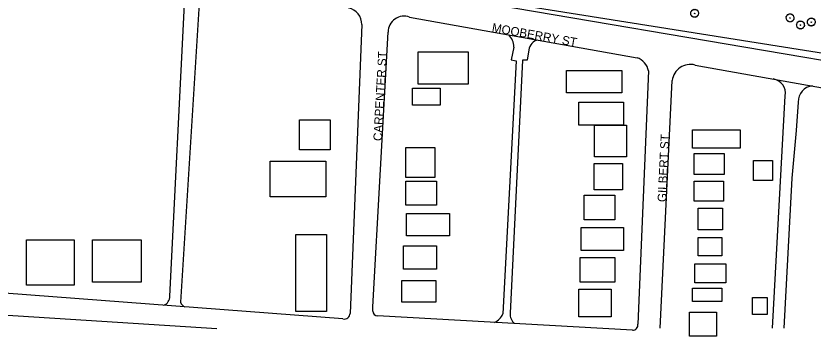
# Model space of a CAD drawing. Extents: x -9648 to 41057, y -12373 to 40276.
# Drawn here: x 11005 to 11921, y -5404 to -5031 of the extents above; entities that cross this region are included whole.
import ezdxf

# ---------------------------------------------------------------- set-up
doc = ezdxf.new("R2010")
doc.units = 0
for name, color, linetype in [('Default', 7, 'Continuous'), ('PM_X_Stop_Line', 7, 'Continuous'), ('SC_Scratch1', 7, 'Continuous'), ('SH_Data', 7, 'Continuous')]:
    doc.layers.add(name, color=color, linetype=linetype)

# ---------------------------------------------------------------- blocks, each defined once
blk = doc.blocks.new('15_PIN')
at = {"layer": 'Default'}
for p, q in [((-2.8, 0), (2.8, 0)), ((0, 2.8), (0, -2.8))]:
    blk.add_line(p, q, dxfattribs=at)
for centre, start, end in [((-25.5, 4.5), 275.99, 64.01), ((-25.9, -1.5), 289.3234, 77.3433), ((-23.8, 10.3), 262.6567, 50.6766), ((-20.8, 15.5), 249.3234, 37.3433), ((-16.7, 19.8), 235.99, 24.01), ((-11.6, 23.2), 222.6567, 10.6766), ((-6, 25.2), 209.3234, 357.3433), ((0, 25.9), 195.99, 344.01), ((6, 25.2), 182.6567, 330.6766), ((11.6, 23.2), 169.3234, 317.3433), ((16.7, 19.8), 155.99, 304.01), ((20.8, 15.5), 142.6567, 290.6766), ((23.8, 10.3), 129.3234, 277.3433), ((25.5, 4.5), 115.99, 264.01), ((25.9, -1.5), 102.6567, 250.6766), ((-24.8, -7.4), 302.6567, 90.6766), ((-22.4, -13), 315.99, 104.01), ((-18.8, -17.8), 329.3234, 117.3433), ((-14.2, -21.6), 342.6567, 130.6766), ((-8.9, -24.3), 355.99, 144.01), ((-3, -25.7), 9.3234, 157.3433), ((3, -25.7), 22.6567, 170.6766), ((8.9, -24.3), 35.99, 184.01), ((14.2, -21.6), 49.3234, 197.3433), ((18.8, -17.8), 62.6567, 210.6767), ((22.4, -13), 75.99, 224.01), ((24.8, -7.4), 89.3234, 237.3433)]:
    blk.add_arc(centre, 3.05, start, end, dxfattribs=at)

msp = doc.modelspace()

# ---------------------------------------------------------------- linework, layer by layer
at = {"layer": 'PM_X_Stop_Line'}
msp.add_arc((9361.23, -8468.95), 3904.03, 82.5, 82.5, dxfattribs=at)
at = {"layer": 'SH_Data'}
for p, q in [((11181.96, -5352.77), (11199.57, -5003.96)), ((11216.16, -5010.15), (11194.36, -5359.76)), ((11514.42, -5006.69), (12381.93, -5145.2)), ((11457.58, -5032.21), (11719, -5078.86)), ((11402.59, -5040.84), (11389.16, -5372.45)), ((11415.36, -5365.04), (11432.79, -5049.43)), ((11785.61, -5087.23), (12022.03, -5129.49)), ((11732, -5094.06), (11719.78, -5385.06)), ((11745.45, -5389.6), (11759.21, -5105.04)), ((11874.44, -5389.53), (11889.22, -5122.57)), ((11380.97, -5378.86), (10992.15, -5349.27)), ((11415.36, -5370.04), (11415.36, -5365.04)), ((10989.77, -5374.28), (11235.9, -5389.89)), ((11713.58, -5391.67), (11420.58, -5375.23))]:
    msp.add_line(p, q, dxfattribs=at)
for points in [[(12047.81, -5101.68), (12020.01, -5096.9), (11026.11, -4928.25), (11019.91, -4926.86)], [(11577.4, -5066.55), (11574.2, -5081.35), (11580, -5082.54), (11564.57, -5373.15)], [(11594.4, -5069.74), (11592.81, -5081.54), (11587.2, -5081.54), (11572.97, -5372.35)], [(11904.23, -5129.76), (11901.66, -5162.56), (11896.69, -5217.37), (11887.61, -5389.52)]]:
    msp.add_lwpolyline(points, dxfattribs=at)
for points in [[(11467.21, -5072.25), (11524.66, -5072.25), (11524.66, -5109.39), (11467.21, -5109.39)], [(11637.8, -5093.47), (11701.44, -5093.47), (11701.44, -5119.11), (11637.8, -5119.11)], [(11461.02, -5113.81), (11492.84, -5113.81), (11492.84, -5133.26), (11461.02, -5133.26)], [(11651.94, -5129.72), (11703.21, -5129.72), (11703.21, -5156.25), (11651.94, -5156.25)], [(11331.09, -5150.06), (11366.45, -5150.06), (11366.45, -5184.54), (11331.09, -5184.54)], [(11669.93, -5156.25), (11706.75, -5156.25), (11706.75, -5192.5), (11669.93, -5192.5)], [(11782.76, -5161.55), (11837.56, -5161.55), (11837.56, -5182.78), (11782.76, -5182.78)], [(11453.07, -5181.89), (11486.66, -5181.89), (11486.66, -5216.37), (11453.07, -5216.37)], [(11784.53, -5188.96), (11819, -5188.96), (11819, -5212.84), (11784.53, -5212.84)], [(11297.5, -5197.81), (11361.14, -5197.81), (11361.14, -5238.48), (11297.5, -5238.48)], [(11669.62, -5200.46), (11702.33, -5200.46), (11702.33, -5230.52), (11669.62, -5230.52)], [(11852.59, -5196.92), (11874.68, -5196.92), (11874.68, -5219.91), (11852.59, -5219.91)], [(11453.07, -5220.8), (11488.42, -5220.8), (11488.42, -5248.2), (11453.07, -5248.2)], [(11784.53, -5220.8), (11818.12, -5220.8), (11818.12, -5243.78), (11784.53, -5243.78)], [(11658.13, -5236.71), (11693.49, -5236.71), (11693.49, -5265), (11658.13, -5265)], [(11788.95, -5251.74), (11817.23, -5251.74), (11817.23, -5276.5), (11788.95, -5276.5)], [(11453.95, -5257.93), (11503.45, -5257.93), (11503.45, -5283.57), (11453.95, -5283.57)], [(11654.6, -5273.85), (11703.21, -5273.85), (11703.21, -5300.37), (11654.6, -5300.37)], [(11326.67, -5281.8), (11362.03, -5281.8), (11362.03, -5370.22), (11326.67, -5370.22)], [(11017.31, -5287.99), (11072.11, -5287.99), (11072.11, -5340.16), (11017.31, -5340.16)], [(11093.32, -5287.99), (11149.01, -5287.99), (11149.01, -5336.62), (11093.32, -5336.62)], [(11788.95, -5285.34), (11816.35, -5285.34), (11816.35, -5306.56), (11788.95, -5306.56)], [(11450.42, -5295.07), (11488.42, -5295.07), (11488.42, -5321.59), (11450.42, -5321.59)], [(11653.71, -5308.33), (11693.49, -5308.33), (11693.49, -5336.62), (11653.71, -5336.62)], [(11785.41, -5315.4), (11820.77, -5315.4), (11820.77, -5337.51), (11785.41, -5337.51)], [(11448.65, -5334.85), (11487.54, -5334.85), (11487.54, -5359.61), (11448.65, -5359.61)], [(11651.94, -5344.58), (11689.07, -5344.58), (11689.07, -5376.41), (11651.94, -5376.41)], [(11782.76, -5343.7), (11816.35, -5343.7), (11816.35, -5358.73), (11782.76, -5358.73)], [(11851.7, -5354.31), (11868.5, -5354.31), (11868.5, -5373.76), (11851.7, -5373.76)], [(11779.22, -5371.11), (11810.16, -5371.11), (11810.16, -5398.52), (11779.22, -5398.52)]]:
    msp.add_lwpolyline(points, close=True, dxfattribs=at)
for centre, radius, start, end in [((11383.46, -5040.57), 19.13, 359.19018, 78.19418), ((11451.33, -5049.67), 18.54, 70.30918, 179.24218), ((11557.79, -5066.57), 19.61, 0.06518, 45.67318), ((11608.09, -5072.05), 13.88, 102.96018, 170.41918), ((11712.11, -5097.93), 20.27, 11.01618, 70.12718), ((11780.25, -5107.75), 21.21, 75.35018, 172.67318), ((11872.65, -5119.85), 16.8, 350.68018, 80.38818), ((11921.64, -5128.73), 17.44, 93.95418, 183.37818), ((11170.75, -5352.96), 11.21, 293.90918, 1.00418), ((11203.3, -5356.41), 9.55, 200.51818, 244.30818), ((11382.22, -5372.02), 6.95, 259.66818, 356.40818), ((11420.84, -5369.75), 5.49, 182.95318, 267.22318), ((11548.23, -5366.62), 17.6, 293.24618, 338.20118), ((11587.82, -5372.74), 14.85, 178.48018, 229.72618), ((11714.21, -5386.04), 5.66, 263.69218, 9.95218)]:
    msp.add_arc(centre, radius, start, end, dxfattribs=at)

# ---------------------------------------------------------------- block references
at = {"layer": 'SH_Data', "xscale": 0.19138193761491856, "yscale": 0.19138193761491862, "rotation": 64.6147239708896}
for p in [(11785.08, -5027.81), (11894.75, -5033.08), (11906.72, -5041.22), (11919.17, -5037.87)]:
    msp.add_blockref('15_PIN', p, dxfattribs=at)

# ---------------------------------------------------------------- texts
at = {"layer": 'SC_Scratch1'}
for s, rotation, p in [('MOOBERRY ST', 349.88142, (11551.54, -5048.9)), ('CARPENTER ST', 86.83844, (11425.79, -5174.77)), ('GILBERT ST', 87.23025, (11752.38, -5244.84))]:
    msp.add_text(s, height=10, rotation=rotation, dxfattribs=at).set_placement(p)

doc.saveas('drawing.dxf')
